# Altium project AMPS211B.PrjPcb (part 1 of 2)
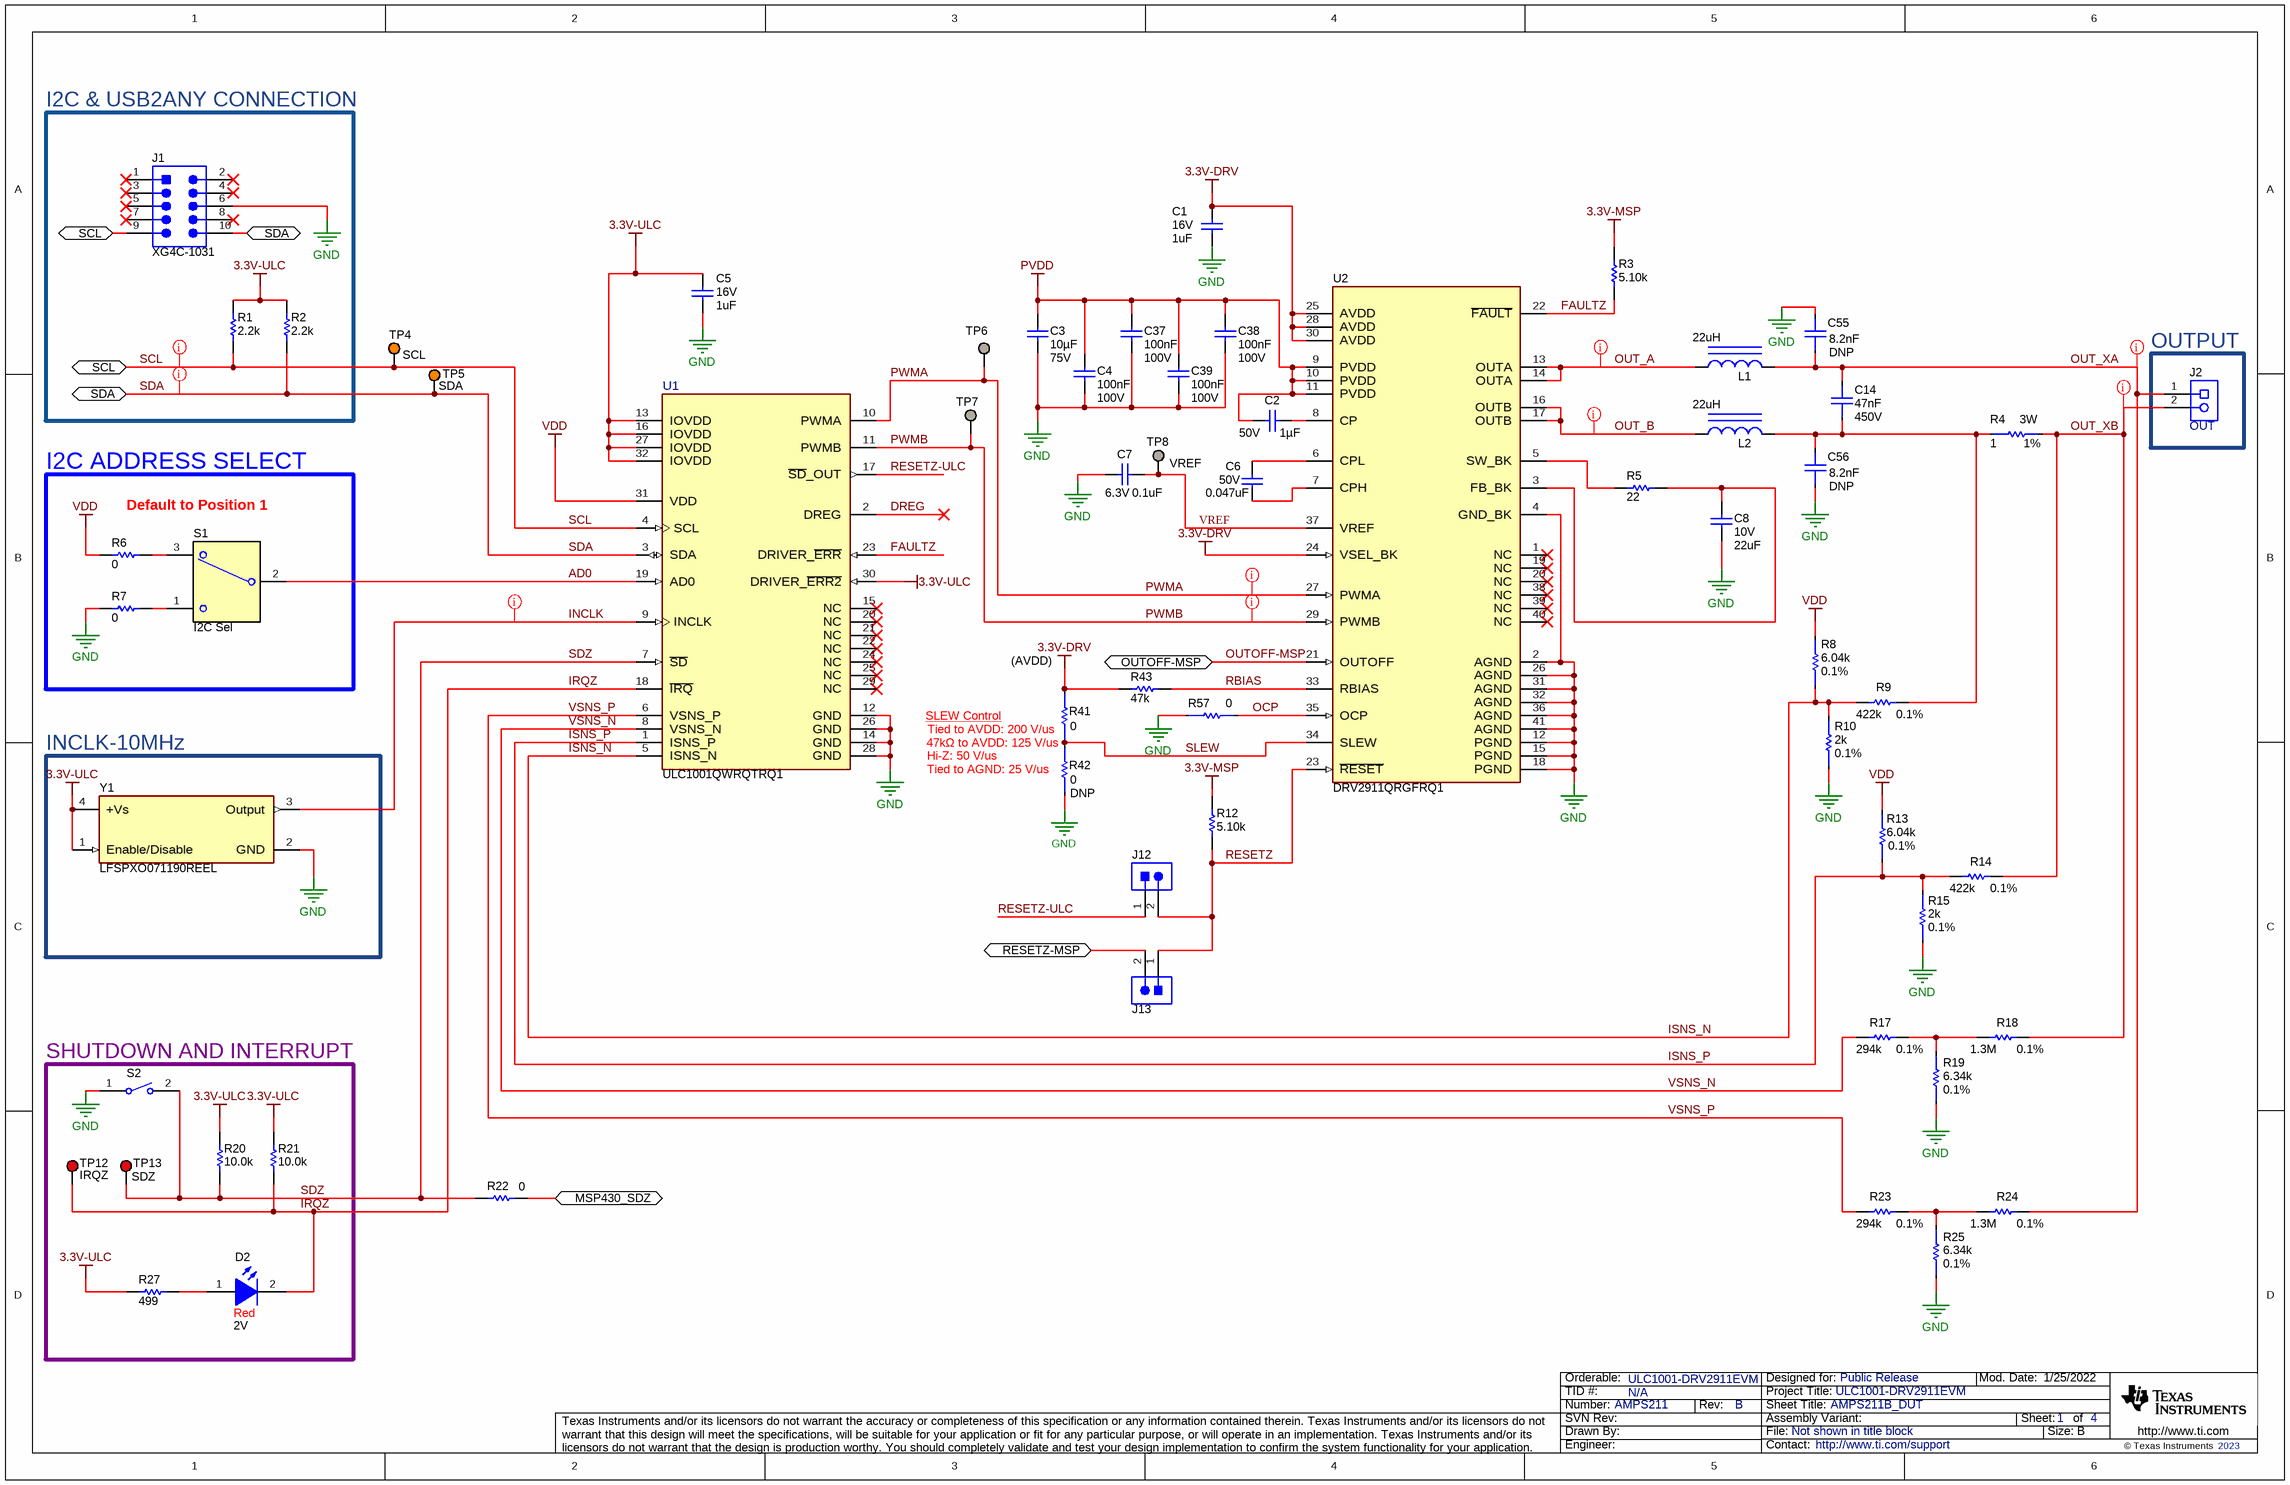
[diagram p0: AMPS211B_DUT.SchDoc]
TID: N/A; TechSupport: http://www.ti.com/support; SCH_Rev: B; PRJ_Title: ULC1001-DRV2911EVM; PRJ_Number: AMPS211; PRJ_Customer: Public Release; PCB_Rev: B; EVM_Orderable: ULC1001-DRV2911EVM; CopyrightYear: 2023
4 sheets, 203 parts. Net scope: flat (ports and power ports of the same name join across sheets).
Board file: AMPS211B.PcbDoc
Sheets:
  AMPS211B_DUT.SchDoc
  AMPS211B_Hardware.SchDoc
  AMPS211B_MSP430.SchDoc
  AMPS211B_PwrMod_Regs.SchDoc

## Sheet AMPS211B_DUT.SchDoc: AMPS211B_DUT
size 431 x 279 mm; Date: Not shown in title block; ApprovedBy: Not shown in title block; CheckedBy: Not shown in title block; Author: Not shown in title block; CompanyName: Not shown in title block; Engineer: Not shown in title block; Organization: Not shown in title block; Address1: Not shown in title block; Address2: Not shown in title block; Address3: Not shown in title block; Address4: Not shown in title block; DocumentNumber: 1; Revision: Use project parameter SCH_Rev; SheetNumber: 1; SheetTotal: 4; PageSetup: Record=PageOptions¦CenterHorizontal=True¦CenterVertical=True¦PrintScale=1.00¦XCorrection=1.00¦YCorrection=1.00¦PrintKind=0¦BorderSize=5000000¦LeftOffset=0¦BottomOffset=0¦Orientation=2¦PaperLength=1000¦PaperWidth=1000¦Scale=100¦PaperSource=15¦PrintQuality=600¦MediaType=1¦DitherType=10¦PaperKind=Letter¦PrintScaleMode=1

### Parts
C1  VDC_V: 16V  ValueDisplayed: 1uF  [0402L]  (hidden comment: EMK105BJ105KVHF)
C2  Cap_F: 1µF  VDC_V: 50V  [0603L]  (hidden comment: UMK107AB7105KA-T)
C3  ValueDisplayed: 10µF  VDC_V: 75V  [1210_280]  (hidden comment: CGA6P1X7R1N106M250AC)
C4  Cap_F: 100nF  VDC_V: 100V  [0603L]  (hidden comment: GRM188R72A104KA35J)
C5  VDC_V: 16V  ValueDisplayed: 1uF  [0402L]  (hidden comment: EMK105BJ105KVHF)
C6  VDC_V: 50V  ValueDisplayed: 0.047uF  [0402L]  (hidden comment: C1005X7R1H473K050BB)
C7  VDC_V: 6.3V  ValueDisplayed: 0.1uF  [0402]  (hidden comment: GRM155R70J104KA01D)
C8  VDC_V: 10V  ValueDisplayed: 22uF  [1206_180L]  (hidden comment: GRM31CR71A226KE15L)
C14  Cap_F: 47nF  VDC_V: 450V  [FP-C2012X7T2W473K125AA_0805-MFG]  (hidden comment: C2012X7T2W473K125AA)
C37  Cap_F: 100nF  VDC_V: 100V  [0603L]  (hidden comment: GRM188R72A104KA35J)
C38  Cap_F: 100nF  VDC_V: 100V  [0603L]  (hidden comment: GRM188R72A104KA35J)
C39  Cap_F: 100nF  VDC_V: 100V  [0603L]  (hidden comment: GRM188R72A104KA35J)
C55  DNP  ValueDisplayed: 8.2nF  [FP-C0805C822JAGACAUTO_0805-MFG]
C56  DNP  ValueDisplayed: 8.2nF  [FP-C0805C822JAGACAUTO_0805-MFG]
D2  value Red  Value2: 2V  [LED_LTST-C170_Red]  (hidden comment: LTST-C170KRKT)
J1  XG4C-1031  [OMRON_XG4C-1031]
J2  OUT  [Molex_039544-3002]
J12  TSW-102-07-T-S  [Samtec_TSW-102-07-T-S]  (value not drawn)
J13  TSW-102-07-T-S  [Samtec_TSW-102-07-T-S]  (value not drawn)
L1  ValueDisplayed: 22uH  [SPM6545VT]  (hidden comment: SPM6545VT-220M-D)
L2  ValueDisplayed: 22uH  [SPM6545VT]  (hidden comment: SPM6545VT-220M-D)
R1  ValueDisplayed: 2.2k  [0402L]  (hidden comment: CRCW04022K20JNED)
R2  ValueDisplayed: 2.2k  [0402L]  (hidden comment: CRCW04022K20JNED)
R3  ValueDisplayed: 5.10k  [0201]  (hidden comment: RC0201FR-075K1L)
R4  Power_W: 3W  Res_ohm: 1  Tolerance_%: 1%  [FP-VMP-1R00-1.0-U_2010-MFG]  (hidden comment: VMP-1R00-1.0-U)
R5  ValueDisplayed: 22  [2512]  (hidden comment: CRCW251222R0JNEGHP)
R6  ValueDisplayed: 0  [0603]  (hidden comment: RC0603JR-070RL)
R7  ValueDisplayed: 0  [0603]  (hidden comment: RC0603JR-070RL)
R8  Res_ohm: 6.04k  Tolerance_%: 0.1%  [FP-TNPW02016K04BEED_0201-MFG]  (hidden comment: TNPW02016K04BEED)
R9  Tolerance_%: 0.1%  ValueDisplayed: 422k  [0603]  (hidden comment: RT0603BRD07422KL)
R10  Res_ohm: 2k  Tolerance_%: 0.1%  [FP-TNPW02012K00BEED_0201-MFG]  (hidden comment: TNPW02012K00BEED)
R12  ValueDisplayed: 5.10k  [0201]  (hidden comment: RC0201FR-075K1L)
R13  Res_ohm: 6.04k  Tolerance_%: 0.1%  [FP-TNPW02016K04BEED_0201-MFG]  (hidden comment: TNPW02016K04BEED)
R14  Tolerance_%: 0.1%  ValueDisplayed: 422k  [0603]  (hidden comment: RT0603BRD07422KL)
R15  Res_ohm: 2k  Tolerance_%: 0.1%  [FP-TNPW02012K00BEED_0201-MFG]  (hidden comment: TNPW02012K00BEED)
R17  Tolerance_%: 0.1%  ValueDisplayed: 294k  [0603]  (hidden comment: RT0603BRD07294KL)
R18  Res_ohm: 1.3M  Tolerance_%: 0.1%  [0603S]  (hidden comment: MCT0603MD1304BP500)
R19  value 6.34k  Tolerance_%: 0.1%  [FP-RT0402BRD076K34L_0402-MFG]  (hidden comment: RT0402BRD076K34L)
R20  ValueDisplayed: 10.0k  [0402S]  (hidden comment: RC0402FR-0710KL)
R21  ValueDisplayed: 10.0k  [0402S]  (hidden comment: RC0402FR-0710KL)
R22  ValueDisplayed: 0  [0402L]  (hidden comment: ERJ-2GE0R00X)
R23  Tolerance_%: 0.1%  ValueDisplayed: 294k  [0603]  (hidden comment: RT0603BRD07294KL)
R24  Res_ohm: 1.3M  Tolerance_%: 0.1%  [0603S]  (hidden comment: MCT0603MD1304BP500)
R25  value 6.34k  Tolerance_%: 0.1%  [FP-RT0402BRD076K34L_0402-MFG]  (hidden comment: RT0402BRD076K34L)
R27  ValueDisplayed: 499  [0402]  (hidden comment: CRCW0402499RFKED)
R41  Res_ohm: 0  [FP-ERJ-H3G0R00V_0603-MFG]
R42  DNP  Res_ohm: 0  [FP-ERJ-H3G0R00V_0603-MFG]
R43  ValueDisplayed: 47k  [0402]  (hidden comment: CRCW040247K0JNED)
R57  value 0  [FP-HCJ0201ZT0R00_0201-MFG]
S1  I2C Sel  [SW_AYZ0102AGRLC]
S2  Shutdown  [SW_EVQ5PN04K]  (value not drawn)
TP4  5013  [Keystone5013]  (value not drawn)
TP5  5013  [Keystone5013]  (value not drawn)
TP6  TP_H0.45P0.75  [TP_H045P075]  (value not drawn)  (no BOM)
TP7  TP_H0.45P0.75  [TP_H045P075]  (value not drawn)  (no BOM)
TP8  TP_H0.45P0.75  [TP_H045P075]  (value not drawn)  (no BOM)
TP12  5010  [Keystone5010]  (value not drawn)
TP13  5010  [Keystone5010]  (value not drawn)
U1  ULC1001QWRQTRQ1  [RQT0032A-MFG]
U2  DRV2911QRGFRQ1  [RGF0040F-MFG]
Y1  LFSPXO071190REEL  [FP-LFSPXO071190REEL_SMT_XTAL_2MM0_1MM6-MFG]

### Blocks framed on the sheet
I2C & USB2ANY CONNECTION: J1 R1 R2
OUTPUT: J2
I2C ADDRESS SELECT: R6 R7 S1
INCLK-10MHz: Y1
SHUTDOWN AND INTERRUPT: D2 R20 R21 R27 S2 TP12 TP13

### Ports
MSP430_SDZ (bidir), OUTOFF-MSP (bidir), RESETZ-MSP (bidir), SCL (bidir), SDA (bidir)

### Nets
3.3V-DRV: C1.1 R41.2 R43.2 U2.24(VSEL_BK) U2.25(AVDD) U2.28(AVDD) U2.30(AVDD)
3.3V-MSP: R3.2 R12.2
3.3V-ULC: C5.1 R1.2 R2.2 R20.1 R21.1 R27.1 U1.13(IOVDD) U1.16(IOVDD) U1.27(IOVDD) U1.30(DRIVER_~{ERR2}) U1.32(IOVDD) Y1.1(Enable/Disable) Y1.4(+Vs)
GND: C1.2 C3.2 C4.2 C5.2 C7.2 C8.2 C37.2 C38.2 C39.2 C55.2 C56.1 J1.6 R7.1 R10.1 R15.1 R19.1 R25.1 R42.1 R57.1 S2.1 U1.12(GND) U1.14(GND) U1.26(GND) U1.28(GND) U2.2(AGND) U2.4(GND_BK) U2.12(PGND) U2.15(PGND) U2.18(PGND) U2.26(AGND) U2.31(AGND) U2.32(AGND) U2.36(AGND) U2.41(AGND) Y1.2(GND)
PVDD: C2.1 C3.1 C4.1 C37.1 C38.1 C39.1 U2.9(PVDD) U2.10(PVDD) U2.11(PVDD)
VDD: R6.1 R8.2 R13.2 U1.31(VDD)
AD0: S1.2(COM) U1.19(AD0)
DREG: U1.2(DREG)
FAULTZ: R3.1 U1.23(DRIVER_~{ERR}) U2.22(~{FAULT})
INCLK: U1.9(INCLK) Y1.3(Output)
IRQZ: D2.2(K) R21.2 TP12.1 U1.18(~{IRQ})
ISNS_N: R8.1 R9.1 R10.2 U1.5(ISNS_N)
ISNS_P: R13.1 R14.1 R15.2 U1.1(ISNS_P)
MSP430_SDZ: R22.2 ; port MSP430_SDZ
OCP: R57.2 U2.35(OCP)
OUT_A: L1.1 U2.13(OUTA) U2.14(OUTA)
OUT_B: L2.1 U2.16(OUTB) U2.17(OUTB)
OUT_XA: C14.2 C55.1 J2.1 L1.2 R24.2
OUT_XB: J2.2 R4.2 R14.2 R18.2
OUTOFF-MSP: U2.21(OUTOFF) ; port OUTOFF-MSP
PWMA: TP6.1 U1.10(PWMA) U2.27(PWMA)
PWMB: TP7.1 U1.11(PWMB) U2.29(PWMB)
RBIAS: R43.1 U2.33(RBIAS)
RESETZ: J12.2 J13.1 R12.1 U2.23(~{RESET})
RESETZ-MSP: J13.2 ; port RESETZ-MSP
RESETZ-ULC: J12.1 U1.17(~{SD}_OUT)
SCL: J1.9 R1.1 TP4.1 U1.4(SCL) ; port SCL
SDA: J1.10 R2.1 TP5.1 U1.3(SDA) ; port SDA
SDZ: R20.2 R22.1 S2.2 TP13.1 U1.7(~{SD})
SLEW: R41.1 R42.2 U2.34(SLEW)
VREF: C7.1 TP8.1 U2.37(VREF)
VSNS_N: R17.1 U1.8(VSNS_N)
VSNS_P: R23.1 U1.6(VSNS_P)
NetC2_2: C2.2 U2.8(CP)
NetC6_1: C6.1 U2.6(CPL)
NetC6_2: C6.2 U2.7(CPH)
NetC8_1: C8.1 R5.2 U2.3(FB_BK)
NetC14_1: C14.1 C56.2 L2.2 R4.1 R9.2
NetD2_1: D2.1(A) R27.2
NetR5_1: R5.1 U2.5(SW_BK)
NetR6_2: R6.2 S1.3
NetR7_2: R7.2 S1.1
NetR17_2: R17.2 R18.1 R19.2
NetR23_2: R23.2 R24.1 R25.2

Not connected (* = marked no-connect by the designer): J1 1* 2* 3* 4* 5* 7* 8*; U1 15(NC)* 20(NC)* 21(NC)* 22(NC)* 24(NC)* 25(NC)* 29(NC)*; U2 1(NC)* 19(NC)* 20(NC)* 38(NC)* 39(NC)* 40(NC)*

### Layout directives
net class Power: OUT_A, OUT_B, OUT_XA, OUT_XB
net class Impedance: INCLK, PWMA, PWMB, SCL, SDA

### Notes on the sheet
- (near TP4) SCL
- (near TP5) SDA
- (near TP8) VREF
- Default to Position 1
- (near R41) (AVDD)
- Hi-Z: 50 V/us
- SLEW Control
- (near R42) Tied to AGND: 25 V/us
- (near R41) Tied to AVDD: 200 V/us
- 47kΩ to AVDD: 125 V/us
- (near TP12) IRQZ
- (near TP13) SDZ

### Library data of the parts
C1 C5 = CMP-0006347-2: CAP, CERM, 1 uF, 16 V, +/- 10%, X5R, 0402; Manufacturer: Taiyo Yuden; TaMin_C: -55°C; Polarized: N; SizeAreaWB_mm2: 3; Value1: Unknown; U/M: EA; Value: 1uF; TaMax_C: 85°C; SizeZ_mm: 0.6; SizeX_mm: 1; SizeY_mm: 0.5; Cap_Case: 0402; Cap_F: 1µF; AEC Category: Q200
C2 = CMP-0007508-5: CAP, CERM, 1 uF, 50 V, +/- 10%, X7R, 0603; Manufacturer: Taiyo Yuden; SizeAreaWB_mm2: 4.68; SizeArea_mm2: 1.28; AEC Category: Q200; Value: 1uF; TaMax_C: 125°C; SizeZ_mm: 1; Polarized: N; TaMin_C: -55°C; SizeY_mm: 0.8; U/M: EA; SizeX_mm: 1.6; Cap_Case: 0603; Value1: Unknown
C3 = CMP-0085951-1: CAP, CERM, 10 µF, 75 V,+/- 20%, X7R, AEC-Q200 Grade 1, 1210; Manufacturer: TDK; SizeX_mm: 3.2; Cap_Case: 1210; AEC Qualified: Y; Polarized: N; AEC Category: Q200; U/M: EA; SizeZ_mm: 2.8; SizeY_mm: 2.5; TaMin_C: -55°C; AEC Grade: 1; SizeAreaWB_mm2: 14.7; SizeArea_mm2: 8; TaMax_C: 125°C; Value: 10uF
C4 C37-C39 = CMP-0007470-5: CAP, CERM, 0.1 uF, 100 V, +/- 10%, X7R, 0603; Manufacturer: MuRata; TaMin_C: -55°C; Polarized: N; SizeAreaWB_mm2: 4.68; Value1: Unknown; U/M: EA; Value: 0.1uF; TaMax_C: 125°C; SizeZ_mm: 1; SizeX_mm: 1.6; SizeY_mm: 0.8; Cap_Case: 0603; SizeArea_mm2: 1.28; AEC Category: Q200
C6 = CMP-0006298-2: CAP, CERM, 0.047 uF, 50 V, +/- 10%, X7R, 0402; Manufacturer: TDK; TaMin_C: -55°C; ESR_ohm: 64.07m; Polarized: N; SizeAreaWB_mm2: 3; Value1: 0.06407 ohm; U/M: EA; SizeZ_mm: 0.6; SizeX_mm: 1; SizeY_mm: 0.5; Cap_Case: 0402; Cap_F: 47nF; IRMS_A: 646.122mA; AEC Category: Q200; TaMax_C: 125°C
C7 = CMP-0006623-2: CAP, CERM, 0.1 uF, 6.3 V, +/- 10%, X7R, 0402; Manufacturer: MuRata; TaMin_C: -55°C; Polarized: N; SizeAreaWB_mm2: 3; Value1: Unknown; U/M: EA; Value: 0.1uF; TaMax_C: 125°C; SizeZ_mm: 0.6; SizeX_mm: 1; SizeY_mm: 0.5; Cap_F: 100nF; AEC Category: Q200
C8 = CMP-0008959-2: CAP, CERM, 22 uF, 10 V, +/- 10%, X7R, 1206; Manufacturer: MuRata; TaMin_C: -55°C; Polarized: N; SizeAreaWB_mm2: 10.92; Value1: Unknown; U/M: EA; Value: 22uF; TaMax_C: 125°C; SizeZ_mm: 1.8; SizeX_mm: 3.2; SizeY_mm: 1.6; Cap_Case: 1206; SizeArea_mm2: 5.12; Cap_F: 22µF; AEC Category: Q200
C14 = CMP-0121787-1: Multilayer Ceramic Capacitors 47nF ±10% 450V X7T SMD 0805; Manufacturer: TDK; AEC Qualified: No; SizeZ_mm: 1.45mm; TempCo: +22/-33%; Tolerance_%: 0.1%
C55 C56 = CMP-0097864-2: C0805 8.2 nF C0G 30ppm/°C 5.00% 250 V; PartNumber: C0805C822JAGACAUTO; Manufacturer: KEMET; VDC_V: 250V; Tolerance_%: 0.05%; AEC Qualified: No; SizeZ_mm: 0.88mm; Value: 8.2nF
D2 = CMP-0002829-3: LED, Red, SMD; Manufacturer: Lite-On; Io_A: 20mA; SizeAreaWB_mm2: 6.75; Value1: W; SizeZ_mm: 1.2; SizeX_mm: 2; SizeY_mm: 1.25; SizeArea_mm2: 2.5; Type: AlInGaP
J1 = CMP-0075051-2: Header (shrouded), 100mil, 5x2, Gold, TH; Manufacturer: Omron Electronic Components; Green_Lifecycle: Not Set; Green_REACh: Incomplete
J2 = CMP-0055345-1: Terminal Block, 5.08mm, 2x1, TH; Manufacturer: Molex; PartNumber: 039544-3002; CNHeader: FALSE; Current_A: 15A; Gender: Female; Voltage_V: 300V; Row_Count: 1; Pitch_mm: 5.08; ContactFinish: Tin; CT: TRUE; Cert_UL: Y
J12 J13 = CMP-0075508-2: Header, 2.54 mm, 2x1, Tin, TH; Manufacturer: Samtec; Pitch_mm: 2.54; Cert_VDE: N; Gender: Male; Cert_CSA: Y; Voltage_V: 550V; Green_REACh: Passed; Current_A: 6.3A; Green_Lifecycle: Active; Row_Count: 1
L1 L2 = CMP-0081476-2: Inductor, Shielded, Metal Composite, 22 µH, 2.4 A, 0.1248 ohm, SMD; Manufacturer: TDK; AEC Qualified: N; DCR_ohm: 0.1248; Ind_H: 22µH; Irms: 2.4A @ 40C rise; Isat: 6.1A @ 30% inductance drop; SizeZ_mm: 4.5; SizeAreaWB_mm2: 76.5; Imax_A: 2.4A; SizeX_mm: 7; SizeY_mm: 6.5; SizeArea_mm2: 45.5; AEC Category: Q200
R1 R2 = CMP-0026890-5: RES, 2.2 k, 5%, 0.063 W, AEC-Q200 Grade 0, 0402; Manufacturer: Vishay-Dale; Power_W: 63mW; TempCo: 200 ppm/C; Value_Code: 2k20; Value: 2.2k; EIA_Code: E24; SizeX_mm: 1; SizeY_mm: 0.5; SizeZ_mm: 0.6; Value2: 0.063W; AEC Qualified: Y; VDC_V: 50V; AEC Category: Q200; AEC Grade: 0
R3 R12 = CMP-0027789-1: RES, 5.10 k, 1%, 0.05 W, 0201; Manufacturer: Yageo America; Power_W: 50mW; TempCo: 200 ppm/C; Value_Code: 5k10; U/M: EA; Value: 5.10k; Res_ohm: 5.1k; SizeX_mm: 0.6; SizeY_mm: 0.3; SizeZ_mm: 0.26; Value2: 0.05W; SizeArea_mm2: 0.18; AEC Qualified: N; VDC_V: 25V; AEC Category: Q200
R4 = CMP-0098465-1: 1 Ohms ±1% 3W Chip Resistor 2010 (5025 Metric) Automotive AEC-Q200, Current Sense, Moisture Resistant, Pulse Withstanding; Manufacturer: Isabellenhuette; AEC Grade: Grade 0; AEC Qualified: Yes; SizeZ_mm: 0.55mm; TempCo: 20ppm/°C; Value: 1
R5 = CMP-0015919-3: RES, 22, 5%, 1.5 W, AEC-Q200 Grade 0, 2512; Manufacturer: Vishay-Dale; Power_W: 1.5W; TempCo: 200 ppm/C; Value_Code: 22R0; Value: 22; EIA_Code: E24; SizeX_mm: 6.3; SizeY_mm: 3.2; SizeZ_mm: 0.71; SizeArea_mm2: 20.16; AEC Qualified: Y; VDC_V: 500V; AEC Category: Q200; AEC Grade: 0
R6 R7 = CMP-0025885-5: RES, 0, 5%, 0.1 W, 0603; Manufacturer: Yageo; Power_W: 100mW; TempCo: 200 ppm/C; Value_Code: 0000; Value: 0; EIA_Code: E24; SizeX_mm: 1.6; SizeZ_mm: 1; Value2: 0.1W; SizeArea_mm2: 1.28; AEC Qualified: N; VDC_V: 75V; AEC Category: Q200; SizeY_mm: 0.8; SizeAreaWB_mm2: 4.68
R8 R13 = CMP-0098454-1: 6.04 kOhms ±0.1% 0.05W, 1/20W Chip Resistor 0201 (0603 Metric) Anti-Sulfur, Automotive AEC-Q200, Moisture Resistant Thin Film; Manufacturer: Vishay; AEC Grade: Grade 0; AEC Qualified: Yes; Power_W: 75mW; SizeZ_mm: 0.26mm; TempCo: 25ppm/°C; VDC_V: 25V; Value: 6.04k
R9 R14 = CMP-0024226-3: RES, 422 k, 0.1%, 0.1 W, 0603; Manufacturer: Yageo America; Power_W: 100mW; TempCo: 25 ppm/C; U/M: EA; Value: 422k; EIA_Code: E192; SizeX_mm: 1.6; SizeY_mm: 0.8; SizeZ_mm: 1; Value2: 0.1W; SizeArea_mm2: 1.28; VDC_V: 75V; AEC Category: Q200
R10 R15 = CMP-0098464-1: 2 kOhms ±0.1% 0.05W, 1/20W Chip Resistor 0201 (0603 Metric) Anti-Sulfur, Automotive AEC-Q200, Moisture Resistant Thin Film; Manufacturer: Vishay Dale; AEC Grade: Grade 0; AEC Qualified: Yes; Power_W: 75mW; SizeZ_mm: 0.26mm; TempCo: 25ppm/°C; VDC_V: 25V; Value: 2k
R17 R23 = CMP-0024046-3: RES, 294 k, 0.1%, 0.1 W, 0603; Manufacturer: Yageo America; Power_W: 100mW; TempCo: 25 ppm/C; U/M: EA; Value: 294k; EIA_Code: E192; SizeX_mm: 1.6; SizeY_mm: 0.8; SizeZ_mm: 1; Value2: 0.1W; SizeArea_mm2: 1.28; VDC_V: 75V; AEC Category: Q200
R18 R24 = CMP-0095259-2: 1.3 MOhms ±0.1% 0.125W, 1/8W Chip Resistor 0603 (1608 Metric) Anti-Sulfur, Automotive AEC-Q200 Thin Film; Manufacturer: Vishay Dale; Power_W: 125mW; TempCo: 25ppm/°C; SizeZ_mm: 0.55mm; Value: 1.3M; VDC_V: 75V; AEC Grade: Grade 0; AEC Qualified: Yes
R19 R25 = CMP-0097226-1: Res Thin Film 0402 6.34K Ohm 0.1% 1/16W ±25ppm/°C Molded SMD Paper T/R; Manufacturer: Yageo; AEC Qualified: No; Power_W: 63mW; VDC_V: 50V; SizeZ_mm: 0.35mm
R20 R21 = CMP-0078669-1: RES, 10.0 k, 1%, 0.063 W, 0402; Manufacturer: Yageo America; Power_W: 63mW; Green_Lifecycle: Active; TempCo: 100 ppm/C; Value_Code: 10k0; Green_REACh: Passed; Value: 10.0k; EIA_Code: E96; Res_ohm: 10k; SizeX_mm: 1; SizeY_mm: 0.5; SizeZ_mm: 0.6; Value2: 0.063W; CompType: Resistor; AEC Qualified: N; AEC Category: Q200
R22 = CMP-0026992-3: RES, 0, 5%, 0.1 W, AEC-Q200 Grade 0, 0402; Manufacturer: Panasonic; Power_W: 100mW; TempCo: 600 ppm/C; Value_Code: 0000; Value: 0; EIA_Code: E24; SizeX_mm: 1; SizeZ_mm: 0.6; Value2: 0.1W; SizeArea_mm2: 0.5; AEC Qualified: Y; VDC_V: 50V; AEC Category: Q200; SizeAreaWB_mm2: 3
R27 = CMP-0026402-2: RES, 499, 1%, 0.063 W, AEC-Q200 Grade 0, 0402; Manufacturer: Vishay-Dale; Power_W: 63mW; TempCo: 100 ppm/C; Value_Code: 499R; Value: 499; EIA_Code: E96; SizeX_mm: 1; SizeY_mm: 0.5; SizeZ_mm: 0.6; Value2: 0.063W; AEC Qualified: Y; VDC_V: 50V; AEC Category: Q200; AEC Grade: 0
R41 R42 = CMP-0097467-1: 0 Ohms Jumper 0.125W, 1/8W Chip Resistor 0603 (1608 Metric) Automotive AEC-Q200 Thick Film; Manufacturer: Panasonic; PartNumber: ERJ-H3G0R00V; VDC_V: 75V; Power_W: 125mW; AEC Qualified: Yes; Value: 0; SizeZ_mm: 0.55mm; AEC Grade: Grade 0
R43 = CMP-0026935-3: RES, 47 k, 5%, 0.063 W, AEC-Q200 Grade 0, 0402; Manufacturer: Vishay-Dale; Power_W: 63mW; TempCo: 200 ppm/C; Value_Code: 47k0; Value: 47k; EIA_Code: E24; SizeX_mm: 1; SizeY_mm: 0.5; SizeZ_mm: 0.6; Value2: 0.063W; AEC Qualified: Y; VDC_V: 50V; AEC Category: Q200; AEC Grade: 0
R57 = CMP-0091760-1: 0 Ohms Jumper 0.1W, 1/10W, 5.8A Chip Resistor 0201 (0603 Metric) Automotive AEC-Q200 Metal Foil; Part Number: HCJ0201ZT0R00; Manufacturer: Stackpole Electronics; AEC Grade: Grade 0; AEC Qualified: Yes; Power_W: 100mW; SizeZ_mm: 0.31mm
S1 = CMP-0002305-1: Switch, SPDT, Slide, On-On, 2 Pos, 0.1 A, 12 VDC, R/A, SMD; PartNumber: AYZ0102AGRLC; Manufacturer: C&K Components; CurrentRating_mA: 100A; PositionCount: 2; SizeX_mm: 7.2; SizeY_mm: 5.3; SizeZ_mm: 1.5; SizeArea_mm2: 38.16; VDC_V: 12V; SizeAreaWB_mm2: 67.16
S2 = CMP-0002323-1: Switch, SPST-NO, Off-Mom, 0.05 A, 12 VDC, SMD; PartNumber: EVQ-5PN04K; Manufacturer: Panasonic; CurrentRating_mA: 50A; PositionCount: 1; SizeX_mm: 7.2; SizeY_mm: 3.5; SizeZ_mm: 4.3; SizeArea_mm2: 25.2; VDC_V: 12V; SizeAreaWB_mm2: 50.6
TP4 TP5 = CMP-0055150-2: Test Point, Multipurpose, Orange, TH; Manufacturer: Keystone Electronics; CT: TRUE; ContactFinish: Silver; Green_REACh: Passed; CNHeader: FALSE; Green_Lifecycle: Active
TP6-TP8 = CMP-0003719-1: Testpoint; Manufacturer: Texas Instruments; CompType: Pad
TP12 TP13 = CMP-0055147-2: Test Point, Multipurpose, Red, TH; Manufacturer: Keystone Electronics; CNHeader: FALSE; Green_Lifecycle: Active; Green_REACh: Passed; ContactFinish: Silver; CT: TRUE
U1 = CMP-0096127-4: Automotive Configurable Ultrasonic PWM Driver With I/V Sense Amplifiers; Part Number: ULC1001RQTR; Manufacturer: Texas Instruments; SizeZ_mm: 1mm; TaMin_C: -40°C; CompType: IC; TaMax_C: +125°C; Standoff Height: 0mm; TJmax_C: +150°C; AEC Category: Q200
U2 = CMP-0049717-3: Full-Bridge PWM Input Piezo Driver for Ultrasonic Lens Cleaning; Manufacturer: Texas Instruments; SizeZ_mm: 1mm; AEC Qualified: Yes; AEC Grade: Grade 1; Max Supply Voltage: 35V; Min Supply Voltage: 4.5V; Nominal Supply Current: 5-19mA; Number Of Drivers: 2; Propagation Delay: 2000ns; Standoff Height: 0mm; TaMax_C: +125°C; TaMin_C: -40°C; TJmax_C: +150°C; AEC Category: Q200; CompType: IC
Y1 = CMP-0088558-2: 10MHz XO (Standard) CMOS Oscillator 3.3V Enable/Disable 4-SMD, No Lead; Manufacturer: IQD; Frequency Stability: 5ppm; Min Supply Voltage: 2.97V; SizeZ_mm: 0.8mm; AEC Grade: Grade 1; Max Supply Voltage: 3.63V; Load Capacitance: 15pF; AEC Qualified: Yes; Max Supply Current: 6mA

## Sheet AMPS211B_Hardware.SchDoc: AMPS211B_Hardware
size 431 x 279 mm; Date: Not shown in title block; ApprovedBy: Not shown in title block; CheckedBy: Not shown in title block; Author: Not shown in title block; CompanyName: Not shown in title block; Engineer: Not shown in title block; Organization: Not shown in title block; Address1: Not shown in title block; Address2: Not shown in title block; Address3: Not shown in title block; Address4: Not shown in title block; DocumentNumber: 4; Revision: Use project parameter SCH_Rev; SheetNumber: 4; SheetTotal: 4; PageSetup: Record=PageOptions¦CenterHorizontal=True¦CenterVertical=True¦PrintScale=1.00¦XCorrection=1.00¦YCorrection=1.00¦PrintKind=0¦BorderSize=5000000¦LeftOffset=0¦BottomOffset=0¦Orientation=2¦PaperLength=1000¦PaperWidth=1000¦Scale=100¦PaperSource=15¦PrintQuality=600¦MediaType=1¦DitherType=10¦PaperKind=Letter¦PrintScaleMode=1
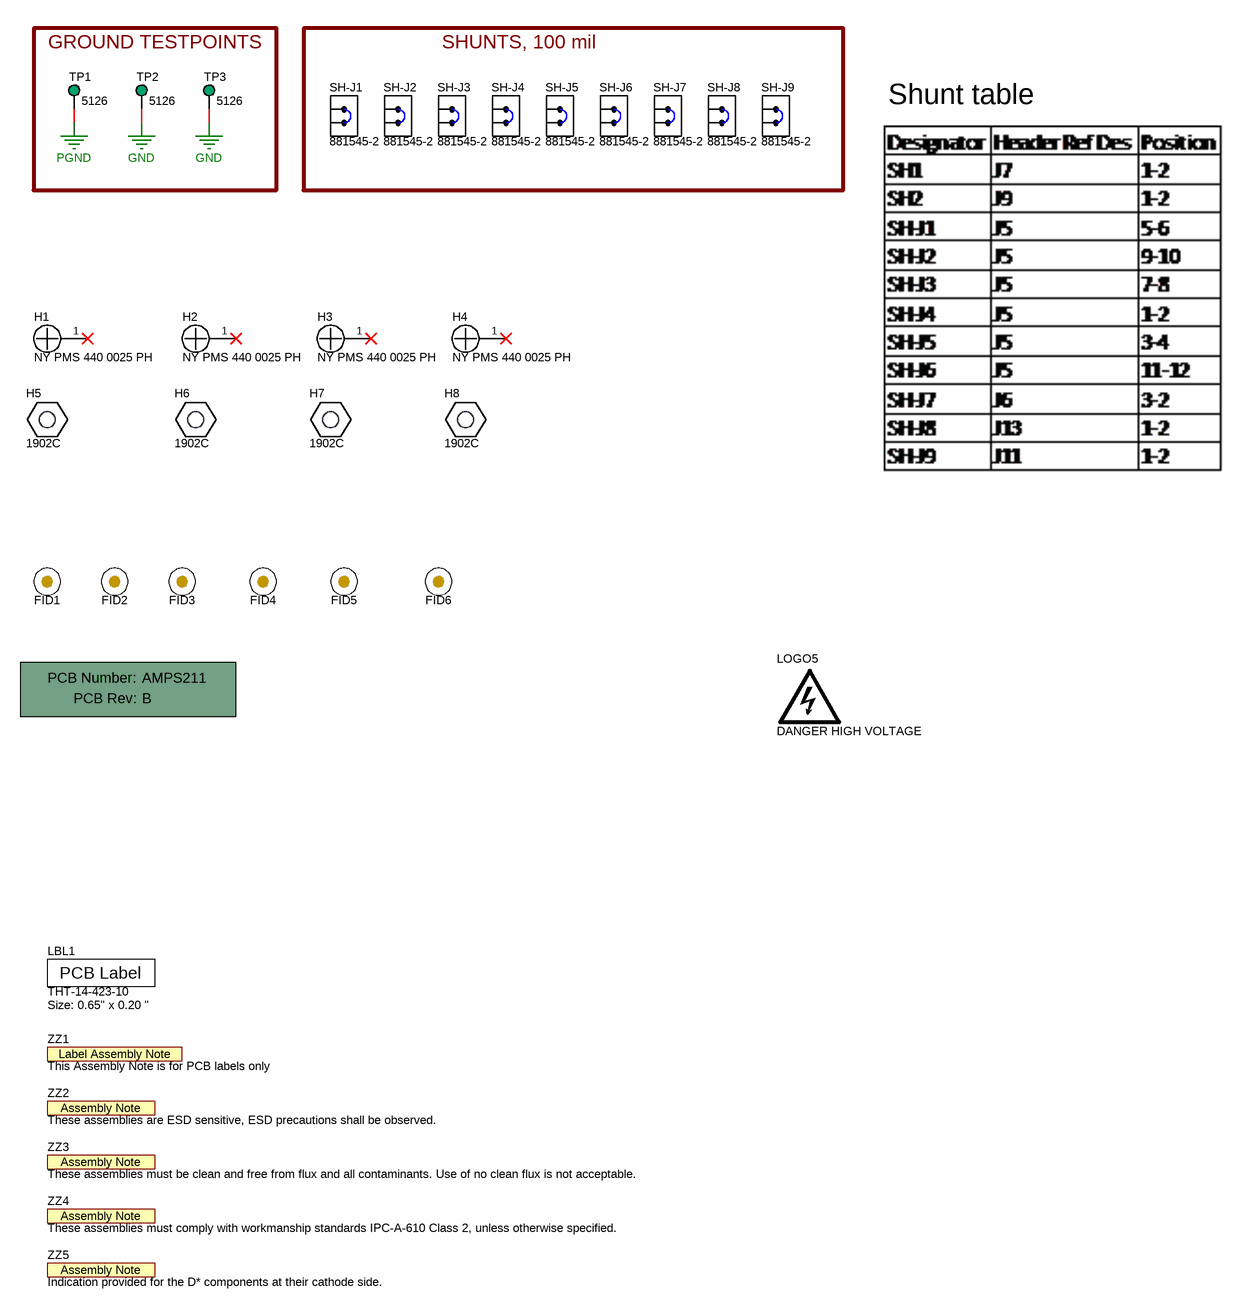
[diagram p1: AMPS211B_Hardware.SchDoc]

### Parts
!PCB  Printed Circuit Board  (value not drawn)  (mechanical)
FID1  Fiducial  [Fiducial10-20]  (value not drawn)
FID2  Fiducial  [Fiducial10-20]  (value not drawn)
FID3  Fiducial  [Fiducial10-20]  (value not drawn)
FID4  Fiducial  [Fiducial10-20]  (value not drawn)
FID5  Fiducial  [Fiducial10-20]  (value not drawn)
FID6  Fiducial  [Fiducial10-20]  (value not drawn)
H1  NY PMS 440 0025 PH  [NY PMS 440 0025 PH]
H2  NY PMS 440 0025 PH  [NY PMS 440 0025 PH]
H3  NY PMS 440 0025 PH  [NY PMS 440 0025 PH]
H4  NY PMS 440 0025 PH  [NY PMS 440 0025 PH]
H5  1902C  [Keystone_1902C]
H6  1902C  [Keystone_1902C]
H7  1902C  [Keystone_1902C]
H8  1902C  [Keystone_1902C]
LBL1  THT-14-423-10  Note: Size: 0.65" x 0.20 "  [Label_650x200]
LOGO5  DANGER HIGH VOLTAGE  [IEC_HighVoltage_Small]  (no BOM)
SH-J1  881545-2  [TE_881545-2]
SH-J2  881545-2  [TE_881545-2]
SH-J3  881545-2  [TE_881545-2]
SH-J4  881545-2  [TE_881545-2]
SH-J5  881545-2  [TE_881545-2]
SH-J6  881545-2  [TE_881545-2]
SH-J7  881545-2  [TE_881545-2]
SH-J8  881545-2  [TE_881545-2]
SH-J9  881545-2  [TE_881545-2]
TP1  5126  [Keystone5126]
TP2  5126  [Keystone5126]
TP3  5126  [Keystone5126]
ZZ1  This Assembly Note is for PCB labels only  [AssemblyNoteLabel]  (no BOM)
ZZ2  These assemblies are ESD sensitive, ESD precautions shall be observed.  [AssemblyNote]  (no BOM)
ZZ3  These assemblies must be clean and free from flux and all contaminants. Use of no clean flux is not acceptable.  [AssemblyNote]  (no BOM)
ZZ4  These assemblies must comply with workmanship standards IPC-A-610 Class 2, unless otherwise specified.  [AssemblyNote]  (no BOM)
ZZ5  Indication provided for the D* components at their cathode side.  [AssemblyNote]  (no BOM)

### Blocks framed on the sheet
GROUND TESTPOINTS: TP1-TP3
SHUNTS, 100 mil: SH-J1-SH-J9

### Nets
GND: TP2.1 TP3.1
PGND: TP1.1

Not connected (* = marked no-connect by the designer): H1 1*; H2 1*; H3 1*; H4 1*

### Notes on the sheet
- Shunt table

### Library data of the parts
!PCB = CMP-0003618-2: Manufacturer: Any; PartNumber: AMPS211
FID1-FID6 = CMP-0077181-1: Fiducial mark.  There is nothing to buy or mount.
H1-H4 = CMP-0003617-1: Machine Screw, Round, #4-40 x 1/4, Nylon, Philips panhead; Manufacturer: B&F Fastener Supply; CompType: Hardware
H5-H8 = CMP-0003610-1: Standoff, Hex, 0.5"L #4-40 Nylon; Manufacturer: Keystone; CompType: Hardware
LBL1 = CMP-0003625-1: Thermal Transfer Printable Labels, 0.650" W x 0.200" H - 10,000 per roll; Manufacturer: Brady; CompType: Label
LOGO5 = CMP-0074835-1: IEC 61010-1 High Voltage Warning; SymbolCreator: a0412235
SH-J1-SH-J9 = CMP-0003677-2: Shunt, 100mil, Gold plated, Black; Manufacturer: TE Connectivity
TP1-TP3 = CMP-0055158-2: Test Point, Multipurpose, Green, TH; Manufacturer: Keystone Electronics; CNHeader: FALSE; Green_Lifecycle: Active; Green_REACh: Passed; ContactFinish: Silver; CT: TRUE
ZZ1 = CMP-0003616-3
ZZ2 = CMP-0077236-1
ZZ3 = CMP-0077237-1
ZZ4 ZZ5 = CMP-0077238-1

## Sheet AMPS211B_MSP430.SchDoc: AMPS211B_MSP430
size 431 x 279 mm; Date: Not shown in title block; ApprovedBy: Not shown in title block; CheckedBy: Not shown in title block; Author: Not shown in title block; CompanyName: Not shown in title block; Engineer: Not shown in title block; Organization: Not shown in title block; Address1: Not shown in title block; Address2: Not shown in title block; Address3: Not shown in title block; Address4: Not shown in title block; DocumentNumber: 3; Revision: Use project parameter SCH_Rev; SheetNumber: 3; SheetTotal: 4; PageSetup: Record=PageOptions¦CenterHorizontal=True¦CenterVertical=True¦PrintScale=1.00¦XCorrection=1.00¦YCorrection=1.00¦PrintKind=0¦BorderSize=5000000¦LeftOffset=0¦BottomOffset=0¦Orientation=2¦PaperLength=1000¦PaperWidth=1000¦Scale=100¦PaperSource=15¦PrintQuality=600¦MediaType=1¦DitherType=10¦PaperKind=Letter¦PrintScaleMode=1
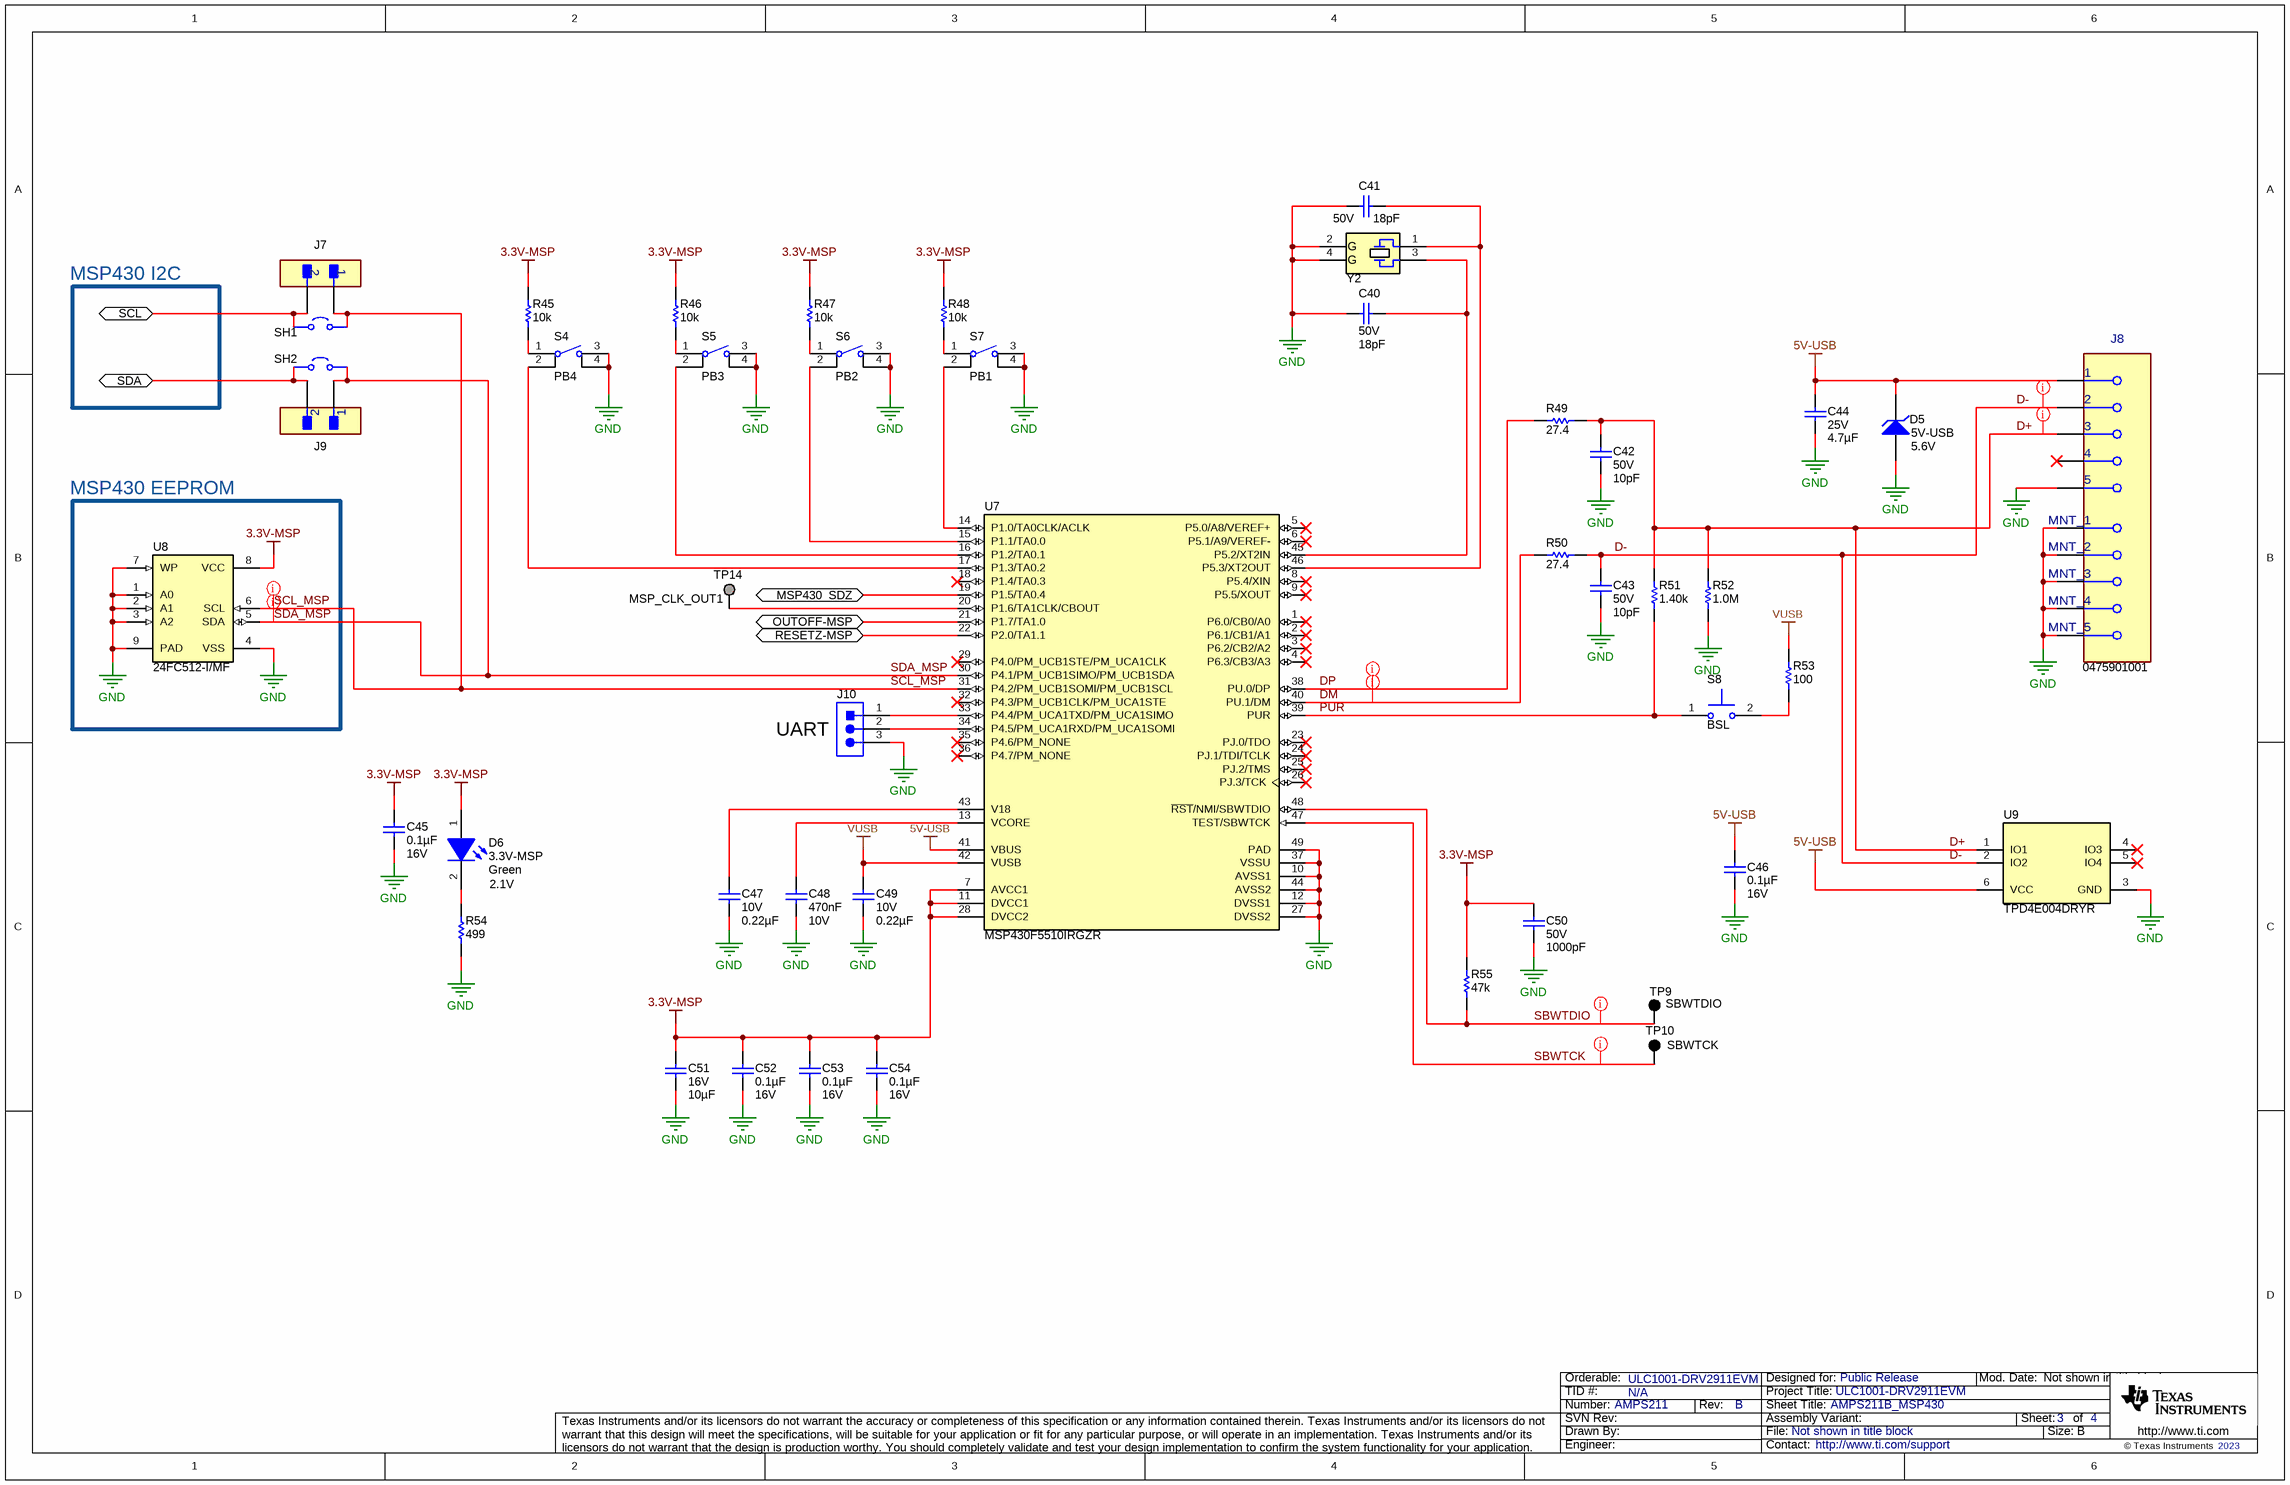
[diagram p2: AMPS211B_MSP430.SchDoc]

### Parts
C40  VDC_V: 50V  ValueDisplayed: 18pF  [0402]  (hidden comment: CL05C180JB5NNNC)
C41  VDC_V: 50V  ValueDisplayed: 18pF  [0402]  (hidden comment: CL05C180JB5NNNC)
C42  VDC_V: 50V  ValueDisplayed: 10pF  [0402]  (hidden comment: CGA2B2C0G1H100D050BA)
C43  VDC_V: 50V  ValueDisplayed: 10pF  [0402]  (hidden comment: CGA2B2C0G1H100D050BA)
C44  VDC_V: 25V  ValueDisplayed: 4.7µF  [1206_180]  (hidden comment: GCM31CR71E475KA55L)
C45  ValueDisplayed: 0.1µF  VDC_V: 16V  [0402]  (hidden comment: EMK105B7104KV-F)
C46  ValueDisplayed: 0.1µF  VDC_V: 16V  [0402]  (hidden comment: EMK105B7104KV-F)
C47  VDC_V: 10V  ValueDisplayed: 0.22µF  [0402]  (hidden comment: LMK105B7224KVHF)
C48  Cap_F: 470nF  VDC_V: 10V  [0603]  (hidden comment: C0603C474K8RACTU)
C49  VDC_V: 10V  ValueDisplayed: 0.22µF  [0402]  (hidden comment: LMK105B7224KVHF)
C50  VDC_V: 50V  ValueDisplayed: 1000pF  [0402]  (hidden comment: C1005NP01H102J050BA)
C51  VDC_V: 16V  ValueDisplayed: 10µF  [0805_150]  (hidden comment: 885012107014)
C52  ValueDisplayed: 0.1µF  VDC_V: 16V  [0402]  (hidden comment: EMK105B7104KV-F)
C53  ValueDisplayed: 0.1µF  VDC_V: 16V  [0402]  (hidden comment: EMK105B7104KV-F)
C54  ValueDisplayed: 0.1µF  VDC_V: 16V  [0402]  (hidden comment: EMK105B7104KV-F)
D5  5V-USB  value 5.6V  [SOD-123]
D6  3.3V-MSP  value Green  Value2: 2.1V  [LED_LTST-C171]
J7  M50-3530242  [FP-M50-3530242_HDR2-MFG]  (value not drawn)
J8  0475901001  [FP-0475901001_CONN_USB_7MM50_5MM90-MFG]
J9  M50-3530242  [FP-M50-3530242_HDR2-MFG]  (value not drawn)
J10  GRPB031VWTC-RC  [Sullins_GRPB031VWTC]  (value not drawn)
R45  ValueDisplayed: 10k  [0402]  (hidden comment: CRCW040210K0JNED)
R46  ValueDisplayed: 10k  [0402]  (hidden comment: CRCW040210K0JNED)
R47  ValueDisplayed: 10k  [0402]  (hidden comment: CRCW040210K0JNED)
R48  ValueDisplayed: 10k  [0402]  (hidden comment: CRCW040210K0JNED)
R49  ValueDisplayed: 27.4  [0603]  (hidden comment: RC0603FR-0727R4L)
R50  ValueDisplayed: 27.4  [0603]  (hidden comment: RC0603FR-0727R4L)
R51  ValueDisplayed: 1.40k  [0402]  (hidden comment: CRCW04021K40FKED)
R52  ValueDisplayed: 1.0M  [0402]  (hidden comment: CRCW04021M00JNED)
R53  ValueDisplayed: 100  [0402]  (hidden comment: CRCW0402100RFKED)
R54  ValueDisplayed: 499  [0603]  (hidden comment: CRCW0603499RFKEAC)
R55  ValueDisplayed: 47k  [0402]  (hidden comment: CRCW040247K0JNED)
S4  PB4  [SW_TL3301_J]
S5  PB3  [SW_TL3301_J]
S6  PB2  [SW_TL3301_J]
S7  PB1  [SW_TL3301_J]
S8  BSL  [SW_TL1015AF160QG]
SH1  M50-2000005  [FP-M50-2000005_CONN_SHUNT2-MFG]  (value not drawn)
SH2  M50-2000005  [FP-M50-2000005_CONN_SHUNT2-MFG]  (value not drawn)
TP9  5011  [Keystone5011]  (value not drawn)
TP10  5011  [Keystone5011]  (value not drawn)
TP14  TP_H0.45P0.75  [TP_H045P075]  (value not drawn)  (no BOM)
U7  MSP430F5510IRGZR  [RGZ0048A]
U8  24FC512-I/MF  [DFNS-MF8]
U9  TPD4E004DRYR  [DRY0006A]
Y2  ABM8-24.000MHZ-B2-T  [XTAL_ABM8]  (value not drawn)

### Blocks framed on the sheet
MSP430 EEPROM: U8

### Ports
MSP430_SDZ (bidir), OUTOFF-MSP (bidir), RESETZ-MSP (bidir), SCL (bidir), SDA (bidir)

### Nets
3.3V-MSP: C45.1 C50.1 C51.1 C52.1 C53.1 C54.1 D6.1(A) R45.2 R46.2 R47.2 R48.2 R55.2 U7.7(AVCC1) U7.11(DVCC1) U7.28(DVCC2) U8.8(VCC)
5V-USB: C44.1 C46.1 D5.1(K) J8.1 U7.41(VBUS) U9.6(VCC)
GND: C40.1 C41.1 C42.2 C43.2 C44.2 C45.2 C46.2 C47.2 C48.2 C49.2 C50.2 C51.2 C52.2 C53.2 C54.2 D5.2(A) J8.5 J8.6(MNT_1) J8.7(MNT_2) J8.8(MNT_3) J8.9(MNT_4) J8.10(MNT_5) J10.3 R52.1 R54.1 S4.3 S4.4 S5.3 S5.4 S6.3 S6.4 S7.3 S7.4 U7.10(AVSS1) U7.12(DVSS1) U7.27(DVSS2) U7.37(VSSU) U7.44(AVSS2) U7.49(PAD) U8.1(A0) U8.2(A1) U8.3(A2) U8.4(VSS) U8.7(WP) U8.9(PAD) U9.3(GND) Y2.2(GND) Y2.4(GND)
VUSB: C49.1 R53.2 U7.42(VUSB)
D+: C42.1 J8.3 R49.2 R51.2 R52.2 U9.1(IO1)
D-: C43.1 J8.2 R50.2 U9.2(IO2)
DM: R50.1 U7.40(PU.1/DM)
DP: R49.1 U7.38(PU.0/DP)
MSP430_SDZ: U7.19(P1.5/TA0.4) ; port MSP430_SDZ
OUTOFF-MSP: U7.21(P1.7/TA1.0) ; port OUTOFF-MSP
PUR: R51.1 S8.1 U7.39(PUR)
RESETZ-MSP: U7.22(P2.0/TA1.1) ; port RESETZ-MSP
SBWTCK: TP10.1 U7.47(TEST/SBWTCK)
SBWTDIO: R55.1 TP9.1 U7.48(~{RST}/NMI/SBWTDIO)
SCL: J7.2 ; port SCL
SCL_MSP: J7.1 U7.31(P4.2/PM_UCB1SOMI/PM_UCB1SCL) U8.6(SCL)
SDA: J9.2 ; port SDA
SDA_MSP: J9.1 U7.30(P4.1/PM_UCB1SIMO/PM_UCB1SDA) U8.5(SDA)
NetC40_2: C40.2 U7.45(P5.2/XT2IN) Y2.3
NetC41_2: C41.2 U7.46(P5.3/XT2OUT) Y2.1
NetC47_1: C47.1 U7.43(V18)
NetC48_1: C48.1 U7.13(VCORE)
NetD6_2: D6.2(K) R54.2
NetJ10_1: J10.1 U7.33(P4.4/PM_UCA1TXD/PM_UCA1SIMO)
NetJ10_2: J10.2 U7.34(P4.5/PM_UCA1RXD/PM_UCA1SOMI)
NetR45_1: R45.1 S4.1
NetR46_1: R46.1 S5.1
NetR47_1: R47.1 S6.1
NetR48_1: R48.1 S7.1
NetR53_1: R53.1 S8.2
NetS4_2: S4.2 U7.17(P1.3/TA0.2)
NetS5_2: S5.2 U7.16(P1.2/TA0.1)
NetS6_2: S6.2 U7.15(P1.1/TA0.0)
NetS7_2: S7.2 U7.14(P1.0/TA0CLK/ACLK)
NetTP14_1: TP14.1 U7.20(P1.6/TA1CLK/CBOUT)

Not connected (* = marked no-connect by the designer): J8 4*; U7 1(P6.0/CB0/A0)* 2(P6.1/CB1/A1)* 3(P6.2/CB2/A2)* 4(P6.3/CB3/A3)* 5(P5.0/A8/VEREF+)* 6(P5.1/A9/VEREF-)* 8(P5.4/XIN)* 9(P5.5/XOUT)* 18(P1.4/TA0.3)* 23(PJ.0/TDO)* 24(PJ.1/TDI/TCLK)* 25(PJ.2/TMS)* 26(PJ.3/TCK)* 29(P4.0/PM_UCB1STE/PM_UCA1CLK)* 32(P4.3/PM_UCB1CLK/PM_UCA1STE)* 35(P4.6/PM_NONE)* 36(P4.7/PM_NONE)*; U9 4(IO3)* 5(IO4)*

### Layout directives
net class Impedance: D+, D-, DM, DP, SBWTCK, SBWTDIO, SCL_MSP, SDA_MSP

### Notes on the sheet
- MSP430 I2C
- (near TP14) MSP_CLK_OUT1
- (near J10) UART
- (near TP9) SBWTDIO
- (near TP10) SBWTCK

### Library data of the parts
C40 C41 = CMP-0860379-1: CAP, CERM, 18 pF, 50 V,+/- 5%, C0G/NP0, 0402; Manufacturer: Samsung Electro-Mechanics; TaMax_C: 125°C; AEC Qualified: N; U/M: EA; Value: 18pF; SizeY_mm: 0.5; AEC Category: Q200; SizeX_mm: 1; SizeAreaWB_mm2: 3; SizeZ_mm: 0.6; TaMin_C: -55°C
C42 C43 = CMP-0006307-2: CAP, CERM, 10 pF, 50 V, +/- 5%, C0G/NP0, AEC-Q200 Grade 1, 0402; Manufacturer: TDK; TaMin_C: -55°C; Polarized: N; SizeAreaWB_mm2: 3; Value1: Unknown; U/M: EA; Value: 10pF; TaMax_C: 125°C; SizeZ_mm: 0.6; SizeX_mm: 1; SizeY_mm: 0.5; AEC Qualified: Y; AEC Category: Q200
C44 = CMP-0082300-1: CAP, CERM, 4.7 µF, 25 V,+/- 10%, X7R, AEC-Q200 Grade 1, 1206; Manufacturer: MuRata; SizeAreaWB_mm2: 10.92; SizeArea_mm2: 5.12; AEC Qualified: Y; AEC Category: Q200; Value: 4.7uF; TaMax_C: 125°C; SizeZ_mm: 1.8; AEC Grade: 1; Polarized: N; TaMin_C: -55°C; SizeY_mm: 1.6; U/M: EA; SizeX_mm: 3.2; Cap_Case: 1206
C45 C46 C52-C54 = CMP-0860188-1: CAP, CERM, 0.1 µF, 16 V,+/- 10%, X7R, 0402; Manufacturer: Taiyo Yuden; SizeX_mm: 1; AEC Category: Q200; Value: 0.1uF; U/M: EA; SizeArea_mm2: 0.5; TaMin_C: -55°C; AEC Qualified: N; SizeAreaWB_mm2: 3; TaMax_C: 125°C; Cap_F: 100nF; SizeZ_mm: 0.6
C47 C49 = CMP-0080612-1: CAP, CERM, 0.22 µF, 10 V,+/- 10%, X7R, AEC-Q200 Grade 1, 0402; Manufacturer: Taiyo Yuden; TaMin_C: -55°C; Polarized: N; SizeAreaWB_mm2: 3; U/M: EA; Value: 0.22uF; TaMax_C: 125°C; SizeZ_mm: 0.6; SizeX_mm: 1; SizeY_mm: 0.5; AEC Qualified: Y; Cap_F: 220nF; AEC Category: Q200
C48 = CMP-0006946-4: CAP, CERM, 0.47 uF, 10 V, +/- 10%, X7R, 0603; Manufacturer: Kemet; Polarized: N; Value: 0.47uF; U/M: EA; Value1: Unknown; TaMin_C: -55°C; TaMax_C: 125°C; AEC Category: Q200; SizeAreaWB_mm2: 4.68; SizeZ_mm: 1; SizeX_mm: 1.6; SizeY_mm: 0.8; SizeArea_mm2: 1.28
C50 = CMP-0006254-2: CAP, CERM, 1000 pF, 50 V, +/- 5%, C0G/NP0, 0402; Manufacturer: TDK; TaMin_C: -55°C; Polarized: N; SizeAreaWB_mm2: 3; Value1: Unknown; U/M: EA; Value: 1000pF; TaMax_C: 150°C; SizeZ_mm: 0.6; SizeX_mm: 1; SizeY_mm: 0.5; Cap_F: 1nF; AEC Category: Q200
C51 = CMP-0078154-1: CAP, CERM, 10 µF, 16 V,+/- 20%, X5R, 0805; Manufacturer: Wurth Elektronik; TaMin_C: -55°C; Polarized: N; SizeAreaWB_mm2: 6.75; U/M: EA; Value: 10uF; TaMax_C: 85°C; SizeZ_mm: 1.5; SizeX_mm: 2; SizeY_mm: 1.25; Cap_Case: 0805; SizeArea_mm2: 2.5; AEC Category: Q200
D5 = CMP-0005803-3: Diode, Zener, 5.6 V, 500 mW, SOD-123; PartNumber: MMSZ5232B-7-F; Manufacturer: Diodes Inc.; RJA_CperW: 350; Power_W: 500mW; SizeZ_mm: 1.35; SizeArea_mm2: 6.545; Value1: 0.5W; SizeAreaWB_mm2: 13.095; AEC Category: Q101; SizeX_mm: 3.85; SizeY_mm: 1.7
D6 = CMP-0002830-3: LED, Green, SMD; Manufacturer: Lite-On; PartNumber: LTST-C171GKT; Type: AlInGaP; Io_A: 20A; Value1: W; SizeArea_mm2: 2.5; SizeZ_mm: 1.2; SizeAreaWB_mm2: 6.75; SizeX_mm: 2; SizeY_mm: 1.25
J7 J9 = CMP-0097269-1: Connector Header Through Hole 2 position 0.050" (1.27mm); Manufacturer: Harwin; AEC Qualified: No; Conn Gender: Male; ContactFinish: Gold,Nickel; Conn Orientation: Vertical; SizeZ_mm: 4.3mm; Current_A: 1A; Row_Count: 1
J8 = CMP-0094459-2: USB - micro AB - Receptacle Connector 5 Position Surface Mount, Right Angle; Through Hole; Manufacturer: Molex; Shrouded: true; Voltage_V: 30V; Usb Standard: USB 2.0; Is Female: yes; ContactFinish: Gold,Nickel; AEC Qualified: No; DUT-Pitch_mm: 0.65mm
J10 = CMP-0054602-1: Header, 1.27mm, 3x1, Gold, SMT; Manufacturer: Sullins Connector Solutions; CNHeader: TRUE; Current_A: 1A; Shrouded: N; Gender: Male; Voltage_V: 500V; Row_Count: 1; Pitch_mm: 1.27; CT: FALSE; Cert_UL: Y
R45-R48 = CMP-0026825-5: RES, 10 k, 5%, 0.063 W, AEC-Q200 Grade 0, 0402; Manufacturer: Vishay-Dale; Power_W: 63mW; TempCo: 200 ppm/C; Value_Code: 10k0; Value: 10k; EIA_Code: E24; SizeX_mm: 1; SizeY_mm: 0.5; SizeZ_mm: 0.6; Value2: 0.063W; AEC Qualified: Y; VDC_V: 50V; AEC Category: Q200; AEC Grade: 0
R49 R50 = CMP-0022967-4: RES, 27.4, 1%, 0.1 W, 0603; Manufacturer: Yageo; Power_W: 100mW; TempCo: 100 ppm/C; Value_Code: 27R4; Value: 27.4; EIA_Code: E96; SizeX_mm: 1.6; SizeY_mm: 0.8; SizeZ_mm: 1; Value2: 0.1W; SizeArea_mm2: 1.28; AEC Qualified: N; VDC_V: 75V; AEC Category: Q200; SizeAreaWB_mm2: 4.68
R51 = CMP-0026085-3: RES, 1.40 k, 1%, 0.063 W, AEC-Q200 Grade 0, 0402; Manufacturer: Vishay-Dale; Power_W: 63mW; TempCo: 100 ppm/C; Value_Code: 1k40; Value: 1.40k; EIA_Code: E96; Res_ohm: 1.4k; SizeX_mm: 1; SizeY_mm: 0.5; SizeZ_mm: 0.6; Value2: 0.063W; AEC Qualified: Y; VDC_V: 50V; AEC Category: Q200; AEC Grade: 0
R52 = CMP-0026859-2: RES, 1.0 M, 5%, 0.063 W, AEC-Q200 Grade 0, 0402; Manufacturer: Vishay-Dale; Power_W: 63mW; TempCo: 200 ppm/C; Value_Code: 1M00; Value: 1.0Meg; EIA_Code: E24; Res_ohm: 1M; SizeX_mm: 1; SizeY_mm: 0.5; SizeZ_mm: 0.6; Value2: 0.063W; AEC Qualified: Y; VDC_V: 50V; AEC Category: Q200; AEC Grade: 0
R53 = CMP-0025951-3: RES, 100, 1%, 0.063 W, AEC-Q200 Grade 0, 0402; Manufacturer: Vishay-Dale; Power_W: 63mW; TempCo: 100 ppm/C; Value_Code: 100R; Value: 100; EIA_Code: E96; SizeX_mm: 1; SizeY_mm: 0.5; SizeZ_mm: 0.6; Value2: 0.063W; AEC Qualified: Y; VDC_V: 50V; AEC Category: Q200; AEC Grade: 0
R54 = CMP-0082532-1: RES, 499, 1%, 0.1 W, 0603; Manufacturer: Vishay-Dale; Value: 499; Value_Code: 499R; Power_W: 100mW; Value2: 0.1W; VDC_V: 75V; TempCo: 100 ppm/C; EIA_Code: E96; SizeAreaWB_mm2: 4.68; SizeX_mm: 1.6; SizeY_mm: 0.8; SizeZ_mm: 1; SizeArea_mm2: 1.28; AEC Qualified: N; AEC Category: Q200
R55 = CMP-0026935-3: as R43 on sheet AMPS211B_DUT
S4-S7 = CMP-0002241-1: Switch, SPST-NO, Off-Mom, 0.05 A, 12 V, SMT; PartNumber: TL3301AF160QJ; Manufacturer: E-Switch; CurrentRating_mA: 50A; PositionCount: 4; VDC_V: 12V
S8 = CMP-0002143-3: Switch, Tactile, SPST-NO, 0.05A, 12V, SMT; PartNumber: TL1015AF160QG; Manufacturer: E-Switch; CurrentRating_mA: 50A; PositionCount: 1; SwitchFunction: Off-Mom
SH1 SH2 = CMP-0097239-3: 1.27 mm, 2 Pos. Female Jumper Socket, Handle Shunt, Black; Manufacturer: Harwin; Current_A: 1A; Is Female: yes; DUT-Pitch_mm: 1.27mm; Row_Count: 1; AEC Qualified: No; Conn Orientation: Vertical; SizeZ_mm: 5.62mm; ContactFinish: Gold,Nickel
TP9 TP10 = CMP-0055148-2: Test Point, Multipurpose, Black, TH; Manufacturer: Keystone Electronics; CNHeader: FALSE; ContactFinish: Silver; Green_REACh: Passed; Green_Lifecycle: Active; CT: TRUE
TP14 = CMP-0003719-1: as TP6 on sheet AMPS211B_DUT
U7 = CMP-0038981-3: Mixed Signal Microcontroller, RGZ0048A (VQFN-48); Manufacturer: Texas Instruments; SizeX_mm: 7; USB: 1; SVS: Yes; USCI_A (UART/LIN/IrDA/SPI): 2; Frequency(MHz): 25; SizeArea_mm2: 49; DMA: 3; GPIO: 47; CompType: IC; SRAM(B): 4096; ADC Channels: 8; ADC: 10-bit SAR; Flash(KB): 32; Timers - 16-bit: 4; Rating: Catalog; AEC Category: Q200; SizeAreaWB_mm2: 81; Multiplier: 32x32
U8 = CMP-0005244-2: 512K I2C Serial EEPROM, DFN-8; Manufacturer: Microchip
U9 = CMP-0043115-3: 4-Channel ESD Protection Array for High-Speed Data Interfaces, DRY0006A (USON-6); Manufacturer: Texas Instruments; IO Leakage Current(nA): 1; USB High Speed: TRUE; IO Capacitance(Typ)(pF): 1.6; Eco-Plan: Green (RoHS & no Sb/Br); IEC 61000-4-2 Contact(+/- kV): 8; Breakdown Voltage(Min)(V): 6; IEC 61000-4-2 Air-Gap(+/- kV): 12; AEC Category: Q200; AEC Qualified: N; CompType: IC; SizeAreaWB_mm2: 4.9; SizeArea_mm2: 1.45; SizeX_mm: 1.0; SizeZ_mm: 0.6; Rating: Catalog
Y2 = CMP-0004583-3: Crystal, 24.000 MHz, 18pF, SMD; Manufacturer: Abracon Corporation; TaMin_C: -20°C; Frequency Stability: +/-50ppm; Frequency_Fixed: 24MHz; TaMax_C: 70°C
